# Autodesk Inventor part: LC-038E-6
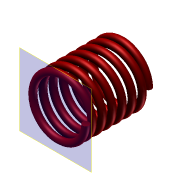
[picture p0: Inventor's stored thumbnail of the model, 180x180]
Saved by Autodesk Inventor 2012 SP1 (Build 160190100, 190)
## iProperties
Created: 2005-12
Part Number: LC-038E-6
Document SubType Name: Modeling
Designer: t_munrn
Mass: 0.129433 g
Surface Area: 5.38002 cm^2
Volume: 0.129433 cm^3
Density: 1 g/cm^3
Material: Default
Author: t_munrn
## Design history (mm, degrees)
sketch "Sketch1"
  geometry: L1 (0, 0)-(0, 9.783); L2 (0, 0)-(4.018, 0); L3 (4.018, 0)-(4.018, 0.483); L4 (4.018, 0.483)-(4.5, 0.483); L5 (4.018, 0.483)-(0, 0.483); A1 r 0.483 centre (4.018, 0.483) between (4.018, 0) and (4.5, 0.483)
  constraints: 10 end point, 4 perpendicular, 2 point on circle, 1 centre point, 1 coincident, 1 point on line, 1 vertical
  dimensions: "d0" = 0.965 diameter of A1; "d1" = 9 diameter of L4.end L1; "d2" = 9.3 distance from line of L1.end L5
coil "Coil1" sketch "Sketch1" pitch "d3" = 10; turns "d5" = 6; dims "d4" = 9.3 (= d2), "d6" = 0, angle "d7" = 90 deg, angle "d8" = 90 deg, "d9" = 90 deg, "d10" = 90 deg
body "Solid1"
